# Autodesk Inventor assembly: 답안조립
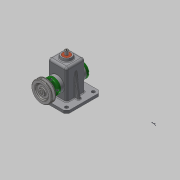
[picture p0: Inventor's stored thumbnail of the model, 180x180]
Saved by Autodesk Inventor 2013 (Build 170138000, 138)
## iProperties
Created: 2016-02
Part Number: 답안조립
Document SubType Name: Assembly
Designer: dgall
Author: dgall
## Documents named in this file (16)
- C:\Users\dgall\Desktop\460211V1003\답안조립.iam
- C:\Users\dgall\Desktop\460211V1003\V벨트풀리.ipt
- C:\Users\dgall\Desktop\460211V1003\고정핀 1.2 x 10.ipt
- C:\Users\dgall\Desktop\460211V1003\뒤커버.ipt
- C:\Users\dgall\Desktop\460211V1003\링크.ipt
- C:\Users\dgall\Desktop\460211V1003\멈춤나사 M3x8.ipt
- C:\Users\dgall\Desktop\460211V1003\베어링 12 x 32 x 10.ipt
- C:\Users\dgall\Desktop\460211V1003\본체.ipt
- C:\Users\dgall\Desktop\460211V1003\볼트 M4 x 12.ipt
- C:\Users\dgall\Desktop\460211V1003\부시.ipt
- C:\Users\dgall\Desktop\460211V1003\슬라이드.ipt
- C:\Users\dgall\Desktop\460211V1003\앞커버.ipt
- C:\Users\dgall\Desktop\460211V1003\오일실 12 25 7.ipt
- C:\Users\dgall\Desktop\460211V1003\키 4 x 4 x 10.ipt
- C:\Users\dgall\Desktop\460211V1003\편심축.ipt
- C:\Users\dgall\Desktop\460211V1003\핀 5 x 18.ipt
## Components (11 placed, 4 different names)
1. V벨트풀리:1
2. 고정핀 1.2 x 10:1
3. 핀 5 x 18:1
4. ISO 4762 M4 x 12:1
5. ISO 4762 M4 x 12:3
6. ISO 4762 M4 x 12:4
7. ISO 4762 M4 x 12:5
8. ISO 4762 M4 x 12:2
9. ISO 4762 M4 x 12:6
10. ISO 4762 M4 x 12:7
11. ISO 4762 M4 x 12:8
